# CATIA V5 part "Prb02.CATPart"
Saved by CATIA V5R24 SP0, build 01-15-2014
Part number: Part1
Bounding box of the stored display mesh (mm): x -46.765 to 150, y -54.83 to 100, z -86.685 to 57.269
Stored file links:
  C:\Users\cdl\Downloads\2024_CAD_midterm\Prb01.CATPart
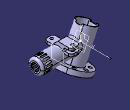
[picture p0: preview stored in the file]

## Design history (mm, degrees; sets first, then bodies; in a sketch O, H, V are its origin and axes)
AxisSystem1: origin (0, 0, 0), X (1, 0, 0), Y (0, 1, 0), Z (0, 0, 1)
Body1 (main body)
  Sketch1 on yz-plane, origin (0, 0, 0), H (0, 1, 0), V (0, 0, 1)
    circle A1 centre (0, 0) radius 25
    radius A1 = 25
  Pad1: profile Sketch1, direction (1, 0, 0), length 150
  Fillet1: radius 8, on edge [face of Pad1 from Sketch1.A1 | end face of Pad1]
  Shell1: ExtOffset 0, Face start face of Pad1, IntOffset 2
  Sketch2 on xy-plane, origin (0, 0, 0), H (1, 0, 0), V (0, 1, 0)
    construction line L1 (120, 0) -> (135, 0)
    point P1 (120, 0)
    point P2 (135, 0)
    line L2 (120, 3) -> (135, 3)
    line L3 (135, -3) -> (120, -3)
    arc A1 centre (135, 0) radius 3 from (135, 3) to (135, -3) cw
    arc A2 centre (120, 0) radius 3 from (120, -3) to (120, 3) cw
    reference projected line E1 (150, 17) -> (150, -17) from edge [face of Fillet1 | end face of Pad1]
    distance L1 L2 = 3
    distance E1 P2 = 15
    length L1 = 15
    coincidence: P1 H
    horizontal: L1 H
    tangency: A1 L2, A2 L2, A1 L3, A2 L3
  Pocket1: profile Sketch2, direction (0, 0, -1), through (limit type 6)
  CircPattern1: of Pocket1, instances 15, angular step 24 {= 360.0*1 deg/CircPattern1.AngularNumber}, axis from face of Pad1 from Sketch1.A1
  Sketch3 on end face of Pad1, origin (150, 2.0618, 6.8382), H (0, 1, 0), V (0, 0, 1)
    point P1 (-2.0618, -6.8382)
    reference projected circle E1 centre (-2.0618, -6.8382) radius 17 from edge [face of Fillet1 | end face of Pad1]
    concentricity: E1 P1
  Hole1: placed by Sketch3, at (150, 0, 0) direction (-1, 0, 0), diameter 25, through (limit type 6)
  Body2
    Sketch4 on zx-plane, origin (0, 0, 0), H (-1, 0, 0), V (0, 0, 1)
      axis line L1 (0, 0) -> (29.3402, 62.9203)
      line L2 (46.5075, 33.4821) -> (-4.2067, -75.2749)
      line L3 (-4.2067, -75.2749) -> (20.2636, -86.6855)
      line L4 (20.2636, -86.6855) -> (26.6029, -73.0909)
      line L5 (26.6029, -73.0909) -> (3.9452, -62.5255)
      line L6 (3.9452, -62.5255) -> (48.3201, 32.6368)
      line L7 (48.3201, 32.6368) -> (46.5075, 33.4821)
      reference projected point E1 (0, 0) from vertex [YZ plane of AxisSystem1 | ZX plane of AxisSystem1 | XY plane of AxisSystem1]
      reference projected point E2 (0, 0) from vertex [YZ plane of AxisSystem1 | ZX plane of AxisSystem1 | XY plane of AxisSystem1]
      reference projected point E3 (0, 0) from vertex [YZ plane of AxisSystem1 | ZX plane of AxisSystem1 | XY plane of AxisSystem1]
      angle L1 V = 25
      length L4 = 15
      distance L3 E1 = 70
      distance L3 L7 = 120
      distance L4 E2 = 55
      distance L6 E3 = 30
      distance L2 L6 = 2
      parallelism: L2 L1, L4 L2, L5 L3
      perpendicularity: L3 L2
    Shaft1: profile Sketch4, axis Sketch4.L1, angle 360
    Sketch5 on face of Shaft1 from Sketch4.L3, origin (50.3333, -35.3328, -53.7656), H (0.9063, 0, 0.4226), V (0, -1, 0)
      point P1 (-64.8951, -35.3328)
      reference projected line E1 through (0, -35.3328) direction (1, 0) from edge [XY plane of AxisSystem1 | ZX plane of AxisSystem1]
      point P2 (-22.8951, -35.3328)
      reference projected circle E2 centre (-22.8951, -35.3328) radius 55 from edge [face of Shaft1 from Sketch4.L3 | face of Shaft1 from Sketch4.L4]
      distance P1 P2 = 42
      coincidence: P1 E1
      concentricity: P2 E2
    Hole2: placed by Sketch5, at (-8.4816, 0, -81.1915) direction (-0.4226, 0, 0.9063), diameter 12, through (limit type 6)
    CircPattern2: of Hole2, instances 8, angular step 45 {= 360.0*1 deg/CircPattern2.AngularNumber}, axis from face of Shaft1 from Sketch4.L6
    Point1: (0, 0, 0), in AxisSystem1
    Line1: type PtDir, RefPoint Point1, Direction zx-plane, Start 0, End 100
    Plane1: type Angle, RefPlane yz-plane, Direction Line1, Angle -25
    Sketch6 on Plane1, origin (0, 0, 0), H (0, 1, 0), V (-0.4226, 0, 0.9063)
      construction line L1 (0, 10) -> (0, -20)
      point P1 (0, 10)
      line L2 (10, 10) -> (10, -20)
      line L3 (-10, -20) -> (-10, 10)
      arc A1 centre (0, -20) radius 10 from (10, -20) to (-10, -20) cw
      arc A2 centre (0, 10) radius 10 from (-10, 10) to (10, 10) cw
      reference projected line E1 (-28, 50) -> (28, 50) from edge [face of Shaft1 from Sketch4.L7 | face of Shaft1 from Sketch4.L2]
      distance L1 L2 = 10
      distance P1 E1 = 40
      length L1 = 30
      vertical: L1 V
      tangency: A1 L2, A2 L2, A1 L3, A2 L3
      coincidence: L1 V
    Pocket2: profile Sketch6, direction (-0.9063, 0, -0.4226), through (limit type 6)
    Sketch7 on Plane1, origin (0, 0, 0), H (0, 1, 0), V (-0.4226, 0, 0.9063)
      point P1 (0, 50)
      line L1 (10, 55) -> (10, 45)
      line L2 (10, 45) -> (-10, 45)
      line L3 (-10, 45) -> (-10, 55)
      line L4 (-10, 55) -> (10, 55)
      reference projected line E1 (-30, 50) -> (30, 50) from edge [face of Shaft1 from Sketch4.L6 | face of Shaft1 from Sketch4.L7]
      length L4 = 20
      length L1 = 10
      vertical: L1 V, L3 V
      horizontal: L2 H, L4 H
      equidistance: L1 L3 P1, L2 L4 P1
      coincidence: E1 P1, P1 V
    Pocket3: profile Sketch7, direction (-0.9063, 0, -0.4226), through (limit type 6), opposite side through (limit type 6)
  Trim1: tool Body2, faces to keep face of Shaft1 from Sketch4.L4; end face of Pad1
  Body3
    Plane2: type Offset, RefPlane yz-plane, Offset 75
    Sketch8 on Plane2, origin (75, 0, 0), H (0, 1, 0), V (0, 0, 1)
      line L1 (-45, 12) -> (45, 12)
      line L2 (45, 12) -> (45, 20)
      line L3 (45, 20) -> (20, 20)
      line L4 (20, 20) -> (20, 29)
      line L5 (20, 29) -> (45, 29)
      line L6 (45, 29) -> (45, 37)
      line L7 (45, 37) -> (0, 37)
      point P8 (0, 37)
      line L8 (0, 37) -> (-17, 20)
      point P9 (-17, 20)
      line L9 (-17, 20) -> (-45, 20)
      line L10 (-45, 20) -> (-45, 12)
      length L2 = 8
      length L6 = 8
      distance L1 L7 = 25
      distance H L1 = 12
      distance V L4 = 20
      distance L10 L2 = 90
      angle L8 L3 = 45
      horizontal: L1 H, L3 H, L5 H, L7 H, L9 H
      vertical: L2 V, L4 V, L6 V, L10 V
      coincidence: P9 L3, P8 V, L6 L2
      symmetry: L2 L10 V
    Pad2: profile Sketch8, direction (-1, 0, 0), length 30
    Fillet2: radius 10, on edge [face of Pad2 from Sketch8.L10 | start face of Pad2]; edge [end face of Pad2 | face of Pad2 from Sketch8.L10]
    Fillet3: radius 10, on edge [face of Pad2 from Sketch8.L6 | start face of Pad2]; edge [face of Pad2 from Sketch8.L2 | start face of Pad2]; edge [end face of Pad2 | face of Pad2 from Sketch8.L6]; edge [end face of Pad2 | face of Pad2 from Sketch8.L2]
    Sketch9 on face of Pad2 from Sketch8.L7, origin (58.2637, 40.3685, 37), H (1, 0, 0), V (0, 1, 0)
      point P1 (1.7363, -5.3685)
      reference projected line E1 (-13.2637, 4.6315) -> (-13.2637, -40.3685) from edge [end face of Pad2 | face of Pad2 from Sketch8.L7]
      reference projected line E2 (16.7363, 4.6315) -> (-13.2637, 4.6315) from edge [face of Pad2 from Sketch8.L6 | face of Pad2 from Sketch8.L7]
      distance E1 P1 = 15
      distance P1 E2 = 10
    Hole3: placed by Sketch9, at (60, 35, 37) direction (0, 0, -1), diameter 10, through (limit type 3)
    Sketch10 on face of Pad2 from Sketch8.L9, origin (57.4974, -37.2908, 20), H (1, 0, 0), V (0, 1, 0)
      point P1 (2.5026, 2.2908)
      reference projected line E1 (-12.4974, 20.2908) -> (-12.4974, -7.7092) from edge [end face of Pad2 | face of Pad2 from Sketch8.L9]
      reference projected line E2 (17.5026, -7.7092) -> (-12.4974, -7.7092) from edge [face of Pad2 from Sketch8.L9 | face of Pad2 from Sketch8.L10]
      distance P1 E1 = 15
      distance P1 E2 = 10
    Hole4: placed by Sketch10, at (60, -35, 20) direction (0, 0, -1), diameter 10, through (limit type 3)
    Fillet4: radius 3, on edge [face of Pad2 from Sketch8.L4 | face of Pad2 from Sketch8.L5]; edge [face of Pad2 from Sketch8.L3 | face of Pad2 from Sketch8.L4]
  Trim2: tool Body3, faces to keep face of Pad2 from Sketch8.L7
